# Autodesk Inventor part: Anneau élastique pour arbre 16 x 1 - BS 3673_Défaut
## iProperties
Shininess: 64.0
Length Units: 11269
Angle Units: 11279
Time Units: 11290
Mass Units: 11283
Length Display Precision: 3
Angle Display Precision: 2
Compacted: True
Part Number: Anneau élastique pour arbre 16 x 1 - BS 3673_Défaut
Document SubType Name: Modeling
Created: 2006-01
Material: Par défaut
Designer: riri
Density: 0.0
Volumn: 0.0
Area: 0.0
PropertySet Name: Model Information
Control State: 0
Master: False
Checked Out: False
Author: riri
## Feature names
1. Base1
